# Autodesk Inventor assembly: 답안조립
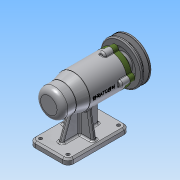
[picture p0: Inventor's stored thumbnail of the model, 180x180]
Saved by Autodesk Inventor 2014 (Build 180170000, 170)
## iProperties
Created: 2019-07
Part Number: 답안조립
Document SubType Name: Assembly
Designer: net
Author: net
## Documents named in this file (12)
- C:\Users\net\Desktop\490704V1004\답안조립.iam
- C:\Users\net\Desktop\490704V1004\답안본체.ipt
- C:\Users\net\Desktop\490704V1004\축.ipt
- C:\Users\net\Desktop\490704V1004\베어링 6004.ipt
- C:\Users\net\Desktop\490704V1004\커버.ipt
- C:\Users\net\Desktop\490704V1004\어댑터슬리브.ipt
- C:\Users\net\Desktop\490704V1004\볼트 M4.ipt
- C:\Users\net\Desktop\490704V1004\베어링 51202.ipt
- C:\Users\net\Desktop\490704V1004\오일 실.ipt
- C:\Users\net\Desktop\490704V1004\V벨트풀리.ipt
- C:\Users\net\Desktop\490704V1004\키 5 x 5 x 16.ipt
- C:\Users\net\Desktop\490704V1004\멈춤나사 M3.ipt
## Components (1 placed, 1 different names)
1. V벨트풀리:1
